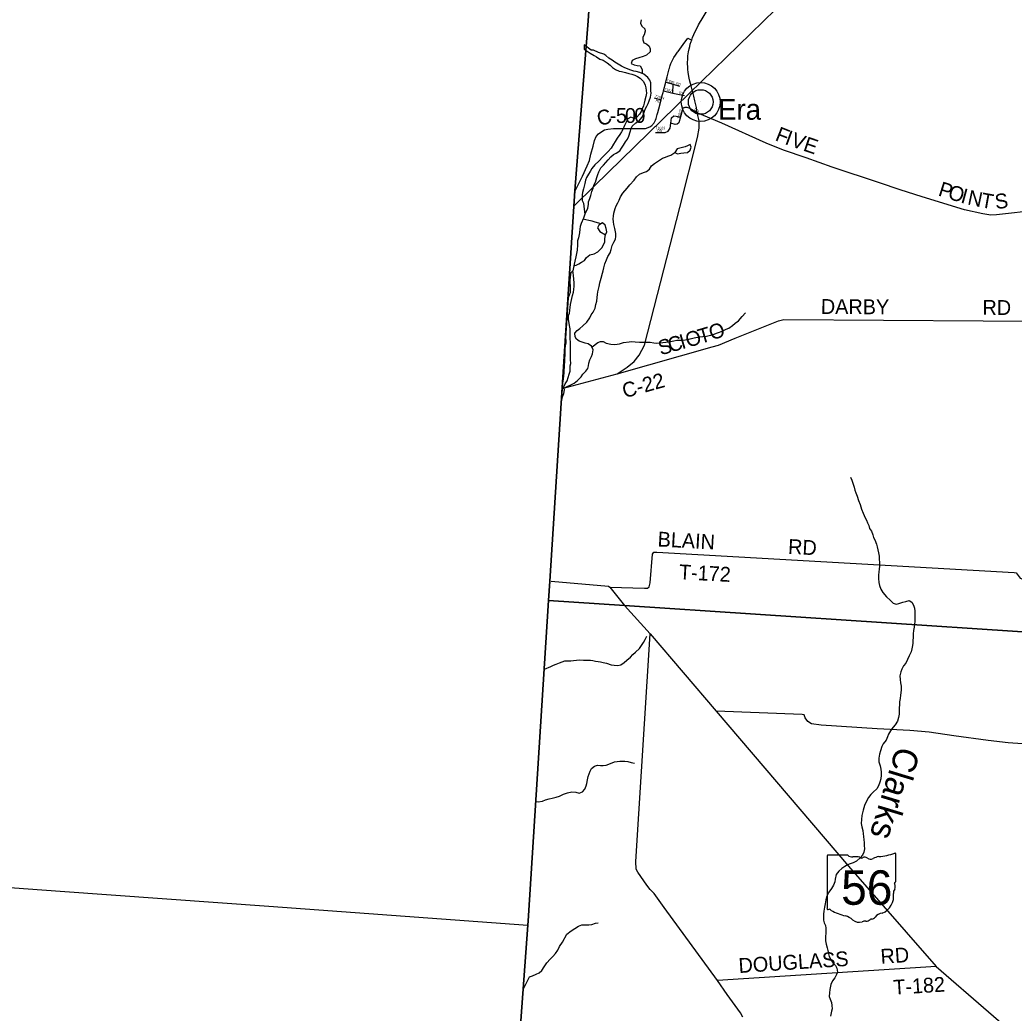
# Model space of a CAD drawing. Extents: x 1643459 to 2064572, y 425441 to 780708.
# Drawn here: x 1746483 to 1766596, y 616581 to 636662 of the extents above; entities that cross this region are included whole.
import ezdxf

# ---------------------------------------------------------------- set-up
doc = ezdxf.new("R2010")
doc.units = 0
for name, color, linetype in [('GE_P_Alignment_100_Curve_Data', 7, 'Continuous'), ('GM_X_City_Street', 7, 'Continuous'), ('GM_X_County', 7, 'Continuous'), ('GM_X_Interchange_Ramps', 7, 'Continuous'), ('GM_X_Interstate_Route', 7, 'Continuous'), ('GM_X_Major_River', 7, 'Continuous'), ('GM_X_Major_River_Text', 7, 'Continuous'), ('GM_X_Minor_Lake', 7, 'Continuous'), ('GM_X_Minor_River', 7, 'Continuous'), ('GM_X_Rail_Line', 7, 'Continuous'), ('GM_X_Section_Text', 7, 'Continuous'), ('GM_X_Township', 7, 'Continuous'), ('GM_X_Township_Road', 7, 'Continuous'), ('GM_X_Township_ROW', 7, 'Continuous'), ('GM_X_Township_Subdivision_Text', 7, 'Continuous'), ('GM_X_Unincorporated_Text', 7, 'Continuous'), ('GM_X_US_Route', 7, 'Continuous'), ('PM_P_Cells', 7, 'Continuous'), ('RD_X_Text', 7, 'Continuous'), ('RD_X_Wall', 7, 'Continuous'), ('ST_Details', 7, 'Continuous')]:
    doc.layers.add(name, color=color, linetype=linetype)

msp = doc.modelspace()

# ---------------------------------------------------------------- linework, layer by layer
at = {"layer": 'GE_P_Alignment_100_Curve_Data'}
for radius in [393, 249]:
    msp.add_circle((1760256, 635002), radius, dxfattribs=at)
at = {"layer": 'GM_X_City_Street'}
for points in [[(1790269, 631741), (1788081, 631718), (1783242, 631666), (1778092, 631612), (1779143, 629082), (1780359, 626159), (1781545, 623306), (1775923, 623680), (1771965, 623943), (1758715, 624823), (1757178, 624925), (1757203, 625316), (1757453, 629228), (1757708, 633208), (1757977, 636642), (1758154, 639332)], [(1755032, 592905), (1755763, 604727), (1756758, 618359), (1756763, 618445), (1757178, 624925), (1758715, 624823), (1771965, 623943), (1775923, 623680), (1781545, 623306), (1781837, 622626), (1785470, 614182), (1787632, 609158), (1789055, 605851), (1790575, 602316), (1791118, 601055), (1793558, 602184), (1795084, 602890), (1794631, 595981)]]:
    msp.add_lwpolyline(points, dxfattribs=at)
at = {"layer": 'GM_X_County'}
for points in [[(1759552, 635405), (1759696, 635362), (1759828, 635324)], [(1759505, 635228), (1759691, 635180), (1759927, 635131)], [(1759691, 635180), (1759696, 635362)], [(1759314, 635088), (1759457, 635049)], [(1759913, 634884), (1759896, 634878), (1759848, 634705), (1759812, 634578), (1759780, 634554), (1759740, 634546), (1759654, 634577)], [(1760184, 634781), (1760020, 634874), (1759980, 634892), (1759934, 634890), (1759924, 634887), (1759913, 634884)], [(1759343, 634384), (1759469, 634387), (1759535, 634383), (1759597, 634410), (1759637, 634472), (1759654, 634577), (1759667, 634685), (1759715, 634719), (1759848, 634705)]]:
    msp.add_lwpolyline(points, dxfattribs=at)
at = {"layer": 'GM_X_Interstate_Route'}
msp.add_lwpolyline([(1792928, 659077), (1789408, 659196), (1786100, 659304), (1784956, 659328), (1781576, 659434), (1779741, 659492), (1773339, 659850), (1771560, 659962), (1771157, 659994), (1759596, 661027), (1759526, 659870), (1759045, 652740), (1758962, 651389), (1758154, 639332), (1757977, 636642), (1757708, 633208), (1757453, 629228), (1757203, 625316), (1757178, 624925), (1756763, 618445), (1756758, 618359), (1755763, 604727), (1755032, 592905)], dxfattribs=at)
at = {"layer": 'GM_X_Major_River_Text'}
for points in [[(1758421, 625192), (1759118, 625175), (1759180, 625174), (1759214, 625196), (1759235, 625280), (1759284, 625860), (1759310, 625902), (1759370, 625900), (1766599, 625487), (1766639, 625483), (1766717, 625372), (1766771, 625352), (1769252, 625185), (1769288, 625191), (1769317, 625233), (1769369, 625594), (1769393, 625623), (1769429, 625637), (1771468, 626355)], [(1772265, 622062), (1771334, 621784), (1771222, 621751), (1771159, 621721), (1771061, 621727), (1767086, 622006), (1766767, 622024), (1766477, 622043), (1766074, 622089), (1765375, 622185), (1764879, 622258), (1764486, 622292), (1763829, 622329), (1762692, 622399), (1762500, 622430), (1762426, 622474), (1762366, 622549), (1762350, 622609), (1762308, 622615), (1760568, 622684)], [(1765022, 617523), (1760593, 617243)]]:
    msp.add_lwpolyline(points, dxfattribs=at)
at = {"layer": 'GM_X_Minor_Lake'}
for points in [[(1757705, 633176), (1757862, 633499), (1757957, 633711), (1758009, 633820), (1758036, 633946), (1758080, 634111), (1758105, 634223), (1758142, 634301), (1758190, 634358), (1758235, 634395), (1758309, 634436), (1758377, 634454), (1758492, 634468), (1758804, 634463), (1759139, 634463), (1759229, 634497), (1759267, 634529), (1759286, 634548), (1759297, 634560), (1759305, 634571), (1759313, 634582), (1759322, 634595), (1759330, 634609), (1759342, 634637), (1759355, 634671), (1759369, 634719), (1759378, 634750), (1759389, 634791), (1759407, 634861), (1759457, 635049), (1759473, 635108), (1759485, 635152), (1759495, 635193), (1759503, 635221), (1759505, 635228), (1759552, 635405), (1759560, 635435), (1759580, 635514), (1759607, 635619), (1759621, 635670), (1759626, 635689), (1759641, 635739), (1759655, 635778), (1759674, 635824), (1759692, 635862), (1759715, 635901), (1759747, 635950), (1759790, 636012), (1759798, 636022), (1759903, 636165), (1759996, 636292), (1760074, 636255)], [(1770000, 630549), (1769738, 630751), (1767875, 632293), (1767488, 632617), (1767305, 632763), (1767251, 632801), (1767205, 632821), (1767083, 632818), (1766239, 632718), (1766124, 632716), (1765966, 632741), (1765594, 632819), (1764734, 633082), (1764288, 633225), (1763876, 633369), (1762914, 633685), (1762390, 633870), (1761928, 634031), (1761582, 634167), (1760684, 634572), (1760184, 634781)], [(1758569, 629508), (1760488, 630050), (1760613, 630088), (1760956, 630230), (1761763, 630549), (1761833, 630579), (1761938, 630603), (1770000, 630549), (1770002, 630601), (1770002, 630601)], [(1761110, 616500), (1761060, 616588), (1760794, 616957), (1760593, 617243), (1759519, 618715), (1759314, 618997), (1759234, 619082), (1759164, 619166), (1758982, 619428), (1758952, 619494), (1758947, 619647), (1759231, 624246)]]:
    msp.add_lwpolyline(points, dxfattribs=at)
at = {"layer": 'GM_X_Minor_River'}
msp.add_lwpolyline([(1742304, 619412), (1747296, 619048), (1751520, 618741), (1756758, 618359), (1756763, 618445), (1757178, 624925), (1757203, 625316), (1757453, 629228), (1757708, 633208), (1757977, 636642), (1758154, 639332), (1758962, 651389), (1759045, 652740), (1759526, 659870), (1759596, 661027), (1759497, 662188)], dxfattribs=at)
at = {"layer": 'GM_X_Rail_Line'}
msp.add_line((1760256, 635002), (1760256, 635002), dxfattribs=at)
at = {"layer": 'GM_X_Township_Road'}
msp.add_lwpolyline([(1757688, 632894), (1758106, 633308), (1760023, 635174), (1763516, 638579)], dxfattribs=at)
at = {"layer": 'GM_X_Township_Subdivision_Text'}
for points in [[(1759735, 633978), (1759789, 633955), (1759851, 633965), (1759917, 633973), (1759986, 633982), (1760040, 634030), (1760060, 634092), (1760045, 634145), (1759988, 634117), (1759944, 634093)], [(1759944, 634093), (1759783, 634052), (1759735, 633978)]]:
    msp.add_lwpolyline(points, dxfattribs=at)
at = {"layer": 'GM_X_Unincorporated_Text'}
for p, q in [((1757899, 636159), (1757896, 636071)), ((1757572, 631040), (1757520, 630224)), ((1757463, 629334), (1757439, 628958))]:
    msp.add_line(p, q, dxfattribs=at)
for points in [[(1757896, 636071), (1757941, 636041), (1758023, 635992), (1758099, 635944), (1758151, 635913), (1758218, 635869), (1758282, 635847), (1758362, 635796), (1758422, 635749), (1758474, 635701), (1758532, 635658), (1758604, 635628), (1758654, 635618), (1758738, 635601), (1758800, 635581), (1758864, 635562), (1758926, 635546), (1758980, 635516), (1759032, 635485), (1759097, 635417), (1759133, 635342), (1759145, 635290), (1759154, 635234), (1759158, 635181), (1759145, 635111), (1759129, 635039), (1759112, 634975), (1759098, 634925), (1759075, 634867), (1759051, 634813), (1759021, 634756), (1758958, 634687), (1758908, 634669), (1758842, 634695), (1758785, 634663), (1758745, 634597), (1758712, 634527), (1758680, 634449), (1758651, 634397), (1758617, 634343), (1758566, 634273), (1758525, 634203), (1758491, 634147), (1758448, 634069), (1758386, 633999), (1758331, 633949), (1758273, 633891), (1758194, 633803), (1758117, 633732), (1758056, 633658), (1758022, 633600), (1757989, 633546), (1757949, 633478), (1757926, 633421), (1757912, 633351), (1757901, 633299), (1757885, 633243), (1757862, 633175), (1757856, 633125), (1757860, 633074), (1757857, 633012), (1757885, 632956), (1757893, 632896), (1757911, 632725)], [(1757911, 632725), (1757940, 632779), (1757970, 632853), (1757987, 632931), (1757989, 632983), (1758012, 633054), (1758036, 633114), (1758057, 633192), (1758078, 633258), (1758094, 633320), (1758125, 633382), (1758155, 633478), (1758174, 633539), (1758194, 633589), (1758239, 633669), (1758293, 633723), (1758384, 633830), (1758435, 633892), (1758491, 633940), (1758548, 633966), (1758622, 634012), (1758655, 634068), (1758691, 634130), (1758732, 634196), (1758778, 634250), (1758805, 634312), (1758830, 634396), (1758846, 634464), (1758870, 634516), (1758941, 634578), (1759010, 634618), (1759066, 634686), (1759099, 634756), (1759121, 634816), (1759142, 634868), (1759168, 634920), (1759195, 634974), (1759215, 635024), (1759238, 635103), (1759252, 635179), (1759248, 635231), (1759246, 635392), (1759228, 635444), (1759184, 635496), (1759106, 635563), (1759024, 635596), (1758952, 635618), (1758900, 635626), (1758824, 635649), (1758708, 635698), (1758652, 635724), (1758587, 635767), (1758521, 635807), (1758463, 635848), (1758399, 635888), (1758335, 635942), (1758295, 635971), (1758190, 636006), (1758085, 636047), (1758043, 636051), (1757899, 636159)], [(1757911, 632725), (1757903, 632711), (1757883, 632653), (1757838, 632545), (1757815, 632483), (1757811, 632428), (1757805, 632356), (1757784, 632256), (1757767, 632198), (1757763, 632111), (1757754, 632005), (1757741, 631941), (1757727, 631871), (1757708, 631784), (1757694, 631726), (1757669, 631590)], [(1757669, 631590), (1757631, 631549), (1757619, 631521), (1757614, 631451), (1757611, 631406)], [(1757665, 631088), (1757680, 631154), (1757688, 631208), (1757695, 631275), (1757693, 631339), (1757688, 631427), (1757682, 631488), (1757677, 631552), (1757669, 631590)], [(1757611, 631406), (1757616, 631234), (1757614, 631152), (1757572, 631040)], [(1757613, 630273), (1757616, 630334), (1757618, 630418), (1757603, 630481), (1757593, 630533), (1757584, 630601), (1757584, 630682), (1757605, 630733), (1757607, 630795), (1757615, 630846), (1757624, 630906), (1757665, 631088)], [(1757520, 630224), (1757526, 630188), (1757527, 630126), (1757517, 630074), (1757510, 630010), (1757507, 629934), (1757507, 629884), (1757504, 629813), (1757499, 629741), (1757495, 629689), (1757492, 629633), (1757490, 629583), (1757485, 629531), (1757480, 629459), (1757476, 629409), (1757467, 629345), (1757463, 629334)], [(1757554, 629366), (1757593, 629497), (1757612, 629559), (1757617, 629612), (1757617, 629669), (1757627, 629717), (1757624, 629796), (1757625, 630002), (1757622, 630081), (1757621, 630149), (1757615, 630215), (1757613, 630273)], [(1757439, 628958), (1757444, 628973), (1757458, 629041), (1757485, 629111), (1757500, 629179), (1757484, 629243), (1757517, 629305), (1757554, 629366)]]:
    msp.add_lwpolyline(points, dxfattribs=at)
at = {"layer": 'GM_X_US_Route'}
for points in [[(1759050, 636663), (1759038, 636593), (1759065, 636535), (1759127, 636482), (1759135, 636432), (1759112, 636362), (1759088, 636310), (1759083, 636256), (1759105, 636201), (1759157, 636179), (1759213, 636131), (1759232, 636074), (1759234, 636014), (1759161, 635950), (1759093, 635922), (1759003, 635893), (1758936, 635877), (1758870, 635841), (1758851, 635781), (1758909, 635751), (1758969, 635740), (1759031, 635736), (1759075, 635662), (1759069, 635586)], [(1757958, 636133), (1757958, 636133)], [(1757490, 629219), (1757695, 629317), (1757761, 629373), (1757838, 629445), (1757873, 629499), (1757929, 629561), (1757976, 629615), (1757988, 629665), (1757992, 629723), (1758011, 629791), (1758050, 629853), (1758064, 629908), (1758079, 629994), (1758049, 630062), (1757981, 630111), (1757921, 630129), (1757855, 630146), (1757795, 630168), (1757743, 630204), (1757714, 630257), (1757712, 630329), (1757754, 630381), (1757809, 630421), (1757873, 630475), (1757952, 630553), (1758013, 630639), (1758043, 630699), (1758082, 630751), (1758119, 630831), (1758135, 630907), (1758154, 630973), (1758160, 631051), (1758169, 631112), (1758175, 631166), (1758200, 631272), (1758218, 631344), (1758245, 631438), (1758268, 631539), (1758284, 631591), (1758299, 631651), (1758319, 631727), (1758348, 631811), (1758379, 631877), (1758423, 631949), (1758446, 632023), (1758466, 632100), (1758501, 632168), (1758531, 632226), (1758538, 632280), (1758536, 632344), (1758517, 632441), (1758499, 632523), (1758490, 632577), (1758486, 632637), (1758493, 632694), (1758499, 632754), (1758524, 632846), (1758544, 632902), (1758577, 632962), (1758605, 633018), (1758636, 633082), (1758684, 633160), (1758767, 633258), (1758820, 633328), (1758909, 633422), (1758955, 633492), (1759016, 633544), (1759100, 633574), (1759159, 633597), (1759217, 633645), (1759262, 633711), (1759322, 633757), (1759399, 633811), (1759483, 633865), (1759542, 633884), (1759592, 633904), (1759654, 633926), (1759735, 633978)], [(1757685, 631692), (1757734, 631704), (1757788, 631728), (1757844, 631762), (1757903, 631797), (1757949, 631859), (1758010, 631915), (1758100, 631935), (1758175, 631971), (1758254, 632053), (1758298, 632125), (1758317, 632175), (1758319, 632243), (1758330, 632317), (1758358, 632379), (1758343, 632446), (1758323, 632510), (1758271, 632560), (1758195, 632515), (1758170, 632459), (1758214, 632386), (1758330, 632317)], [(1758243, 632540), (1758121, 632575), (1758061, 632590), (1757991, 632604), (1757870, 632630)], [(1757675, 631639), (1757676, 631643)], [(1757598, 631320), (1757599, 631317)], [(1758059, 630050), (1758176, 630138), (1758228, 630158), (1758284, 630159), (1758346, 630125), (1758438, 630106), (1758522, 630102), (1758613, 630115), (1758695, 630137), (1758808, 630154), (1758858, 630160), (1758928, 630152), (1759016, 630149), (1759070, 630149), (1759152, 630149), (1759231, 630144), (1759309, 630134), (1759361, 630129), (1759427, 630131), (1759487, 630137), (1759549, 630148), (1759614, 630156), (1759710, 630172), (1759774, 630185), (1759836, 630189), (1759896, 630187), (1759995, 630198), (1760045, 630216), (1760123, 630236), (1760230, 630251), (1760302, 630261), (1760372, 630266), (1760426, 630278), (1760495, 630292), (1760575, 630328), (1760633, 630347), (1760704, 630373), (1760774, 630407), (1760827, 630431), (1760899, 630486), (1760956, 630528), (1761018, 630580), (1761097, 630662), (1761164, 630740)], [(1763285, 627418), (1763315, 627354), (1763343, 627275), (1763360, 627217), (1763376, 627155), (1763397, 627100), (1763419, 627030), (1763449, 626947), (1763480, 626867), (1763511, 626772), (1763545, 626686), (1763580, 626597), (1763612, 626547), (1763628, 626495), (1763657, 626442), (1763673, 626382), (1763709, 626324), (1763736, 626253), (1763754, 626199), (1763780, 626147), (1763815, 626062), (1763827, 626008), (1763840, 625950), (1763854, 625889), (1763864, 625817), (1763869, 625751), (1763871, 625696), (1763870, 625620), (1763868, 625556), (1763859, 625504), (1763855, 625432), (1763852, 625371), (1763860, 625289), (1763871, 625229), (1763903, 625150), (1763943, 625084), (1764012, 624995), (1764090, 624928), (1764152, 624870), (1764212, 624851), (1764262, 624865), (1764342, 624889), (1764407, 624903), (1764471, 624922), (1764529, 624888), (1764562, 624827), (1764578, 624771), (1764588, 624705), (1764589, 624639), (1764591, 624588), (1764590, 624496), (1764584, 624444), (1764573, 624384), (1764563, 624313), (1764556, 624247), (1764554, 624177), (1764549, 624115), (1764547, 624063), (1764541, 624012), (1764526, 623948), (1764512, 623884), (1764475, 623802), (1764440, 623730), (1764404, 623658), (1764359, 623602), (1764325, 623534), (1764302, 623482), (1764286, 623402), (1764291, 623325), (1764301, 623261), (1764310, 623191), (1764310, 623112), (1764299, 623010), (1764288, 622942), (1764280, 622871), (1764277, 622817), (1764273, 622743), (1764270, 622675), (1764268, 622623), (1764260, 622556), (1764239, 622484), (1764192, 622410), (1764118, 622320), (1764057, 622218), (1764032, 622168), (1764008, 622100), (1763947, 622028), (1763917, 621972), (1763894, 621884), (1763871, 621814), (1763861, 621733), (1763862, 621659), (1763884, 621581), (1763901, 621510), (1763907, 621450), (1763906, 621394), (1763900, 621320), (1763881, 621251), (1763851, 621175), (1763820, 621113), (1763748, 621049)], [(1757505, 623702), (1757629, 623703), (1757681, 623712), (1757745, 623718), (1757804, 623720), (1757882, 623717), (1757954, 623719), (1758024, 623717), (1758076, 623708), (1758126, 623698), (1758182, 623690), (1758232, 623681), (1758284, 623667), (1758348, 623655), (1758443, 623624), (1758505, 623616), (1758581, 623609), (1758643, 623623), (1758710, 623671), (1758764, 623719), (1758833, 623780), (1758885, 623834), (1758938, 623878), (1759018, 623952), (1759061, 624010), (1759097, 624076), (1759130, 624132), (1759168, 624204)], [(1757093, 623537), (1757225, 623587), (1757276, 623616), (1757330, 623637), (1757401, 623661), (1757505, 623702)], [(1757480, 621007), (1757562, 621035), (1757648, 621056), (1757729, 621048), (1757795, 621027), (1757863, 621055), (1757913, 621109), (1757940, 621173), (1757950, 621223), (1757965, 621300), (1757979, 621362), (1757998, 621418), (1758020, 621474), (1758045, 621524), (1758105, 621574), (1758167, 621592), (1758230, 621589), (1758286, 621587), (1758342, 621591), (1758398, 621612), (1758511, 621660), (1758619, 621676), (1758723, 621675), (1758782, 621665), (1758850, 621648), (1758914, 621632)], [(1756907, 620868), (1756971, 620851), (1757053, 620868), (1757118, 620894), (1757188, 620915), (1757252, 620928), (1757333, 620947), (1757399, 620966), (1757480, 621007)], [(1763748, 621049), (1763697, 621001), (1763651, 620943), (1763598, 620837), (1763569, 620781), (1763541, 620687), (1763532, 620629), (1763518, 620575), (1763511, 620494), (1763499, 620412), (1763518, 620350), (1763536, 620273), (1763543, 620203), (1763549, 620153), (1763554, 620084), (1763560, 620028), (1763566, 619968), (1763569, 619904), (1763559, 619833), (1763528, 619777), (1763482, 619723), (1763411, 619652), (1763340, 619616), (1763282, 619600), (1763228, 619576), (1763172, 619548), (1763111, 619505), (1763053, 619451), (1762998, 619383), (1762975, 619292), (1762969, 619234), (1762944, 619164), (1762904, 619098), (1762845, 619026), (1762806, 618948), (1762788, 618874), (1762775, 618787), (1762763, 618721), (1762750, 618645), (1762740, 618579), (1762737, 618517), (1762741, 618458), (1762754, 618408), (1762778, 618350), (1762786, 618297), (1762789, 618245), (1762785, 618193), (1762781, 618139), (1762778, 618042), (1762796, 617976), (1762815, 617900), (1762827, 617849), (1762838, 617779), (1762858, 617727), (1762895, 617650), (1762939, 617592), (1762983, 617541), (1763007, 617489), (1763024, 617410), (1763002, 617358), (1762971, 617294), (1762925, 617230), (1762888, 617162), (1762865, 617060), (1762859, 616993), (1762852, 616915), (1762876, 616861), (1762903, 616798), (1762911, 616734), (1762913, 616670), (1762904, 616620), (1762885, 616521)], [(1757458, 618012), (1757550, 618175), (1757636, 618247), (1757713, 618293), (1757782, 618341), (1757854, 618368), (1757932, 618366), (1757994, 618366), (1758054, 618375), (1758129, 618397), (1758183, 618409)], [(1756664, 617060), (1756792, 617312), (1756851, 617334), (1756930, 617371), (1756986, 617392), (1757045, 617444), (1757090, 617515), (1757143, 617595), (1757208, 617672), (1757265, 617726), (1757316, 617785), (1757367, 617855), (1757402, 617925), (1757458, 618012)]]:
    msp.add_lwpolyline(points, dxfattribs=at)
at = {"layer": 'RD_X_Text'}
msp.add_lwpolyline([(1757232, 625314), (1758391, 625211), (1758421, 625192), (1758715, 624823), (1759231, 624246), (1760568, 622684), (1763244, 619552), (1765022, 617523), (1767140, 615688), (1768855, 614819), (1771492, 613520), (1772414, 613091), (1772539, 613016), (1772653, 612916), (1773673, 611884), (1773774, 611775), (1773945, 611670), (1774091, 611580), (1776024, 610826)], dxfattribs=at)
at = {"layer": 'RD_X_Wall'}
msp.add_lwpolyline([(1757453, 629211), (1758569, 629508), (1758768, 629638), (1758910, 629755), (1759010, 629881), (1759119, 630086), (1759832, 632867), (1760193, 634283), (1760223, 634476), (1760227, 634624), (1760184, 634781), (1760179, 634827), (1760169, 634888), (1760158, 634943), (1760138, 635025), (1760115, 635118), (1760094, 635204), (1760090, 635220), (1760061, 635331), (1760038, 635423), (1760024, 635487), (1760011, 635558), (1760004, 635604), (1759998, 635656), (1759994, 635715), (1759992, 635774), (1759996, 635894), (1759996, 635900), (1759999, 635936), (1760011, 636017), (1760022, 636075), (1760033, 636127), (1760046, 636174), (1760064, 636228), (1760074, 636255), (1760093, 636305), (1760118, 636365), (1760212, 636565), (1760418, 636909)], dxfattribs=at)
at = {"layer": 'ST_Details'}
for p, q in [((1762811, 619753), (1762811, 618697)), ((1763232, 619771), (1762824, 619771)), ((1764203, 619245), (1764203, 619798)), ((1764203, 619245), (1764203, 619245))]:
    msp.add_line(p, q, dxfattribs=at)
for centre, radius, start, end in [((1762827, 619755), 16.1, 98.1301, 188.1301), ((1763329, 619894), 156, 231.6195, 271.1119), ((1763381, 619178), 562, 80.4867, 94.9883), ((1763508, 619761), 45.1, 219.7921, 297.1024), ((1763575, 619639), 93.8, 54.4667, 119.1411), ((1763696, 619806), 113, 233.8562, 294.8282), ((1763895, 619449), 297, 97.3462, 120.7689), ((1763707, 621212), 1476, 275.8445, 288.9065), ((1764187, 619800), 15.5, 351.8621, 97.738), ((1764258, 619013), 105, 136.8065, 186.9296), ((1764199, 619204), 24, 107.944, 210.337), ((1764047, 619134), 144, 340.033, 23.6496), ((1764186, 619243), 16.6, 289.6038, 7.7341), ((1763790, 618943), 369, 292.3089, 8.9858), ((1762827, 618694), 16.3, 171.9584, 258.3066), ((1762829, 618802), 124, 267.339, 280.6039), ((1762855, 618636), 44.8, 29.7484, 93.2717), ((1763420, 619585), 1066, 240.4129, 257.1985), ((1763102, 618222), 334, 47.1842, 75.836), ((1763703, 618449), 31.8, 65.7517, 132.6484), ((1763689, 618594), 119, 282.8732, 323.2771), ((1763945, 618400), 202, 94.4031, 142.5768), ((1763463, 618630), 212, 230.7004, 286.2918), ((1763585, 618265), 174, 85.6951, 111.2099), ((1763601, 618551), 113, 268.777, 315.5493)]:
    msp.add_arc(centre, radius, start, end, dxfattribs=at)

# ---------------------------------------------------------------- texts
at = {"layer": 'GM_X_Interchange_Ramps'}
msp.add_text('Clarks', height=500.1, rotation=253.1181, dxfattribs=at).set_placement((1764222, 621998))
at = {"layer": 'GM_X_Major_River'}
for s, rotation, p in [('BLAIN', 356.8698, (1759378, 626017)), ('RD', 357.0388, (1762018, 625867)), ('T-172', 356.9131, (1759810, 625354)), ('RD', 3.9449, (1763904, 617575)), ('DOUGLASS', 3.7453, (1761031, 617390)), ('T-182', 3.6632, (1764161, 616950))]:
    msp.add_text(s, height=300, rotation=rotation, dxfattribs=at).set_placement(p)
at = {"layer": 'GM_X_Section_Text'}
for s, rotation, p in [('C', 15.8095, (1758204, 634511)), ('5', 359.5622, (1758540, 634580)), ('0', 359.6063, (1758723, 634579)), ('0', 1.2544, (1758916, 634578)), ('-', 2.7959, (1758422, 634575)), ('F', 338.4315, (1761744, 634233)), ('I', 339.9202, (1761940, 634156)), ('V', 340.8299, (1762060, 634112)), ('E', 341.0307, (1762311, 634025)), ('P', 342.4756, (1765044, 633114)), ('O', 342.728, (1765238, 633053)), ('I', 344.5872, (1765500, 632972)), ('N', 347.985, (1765638, 632934)), ('T', 349.8723, (1765907, 632877)), ('S', 6.9788, (1766225, 632835)), ('DARBY', 359.6208, (1762686, 630718)), ('RD', 359.5064, (1765955, 630700)), ('O', 16.0059, (1759995, 630035)), ('T', 16.3321, (1760250, 630108)), ('O', 19.6412, (1760483, 630177)), ('S', 16.0061, (1759445, 629877)), ('C', 16.0028, (1759639, 629933)), ('I', 16.0078, (1759876, 630001)), ('C-22', 15.6153, (1758716, 629011))]:
    msp.add_text(s, height=300, rotation=rotation, dxfattribs=at).set_placement(p)
at = {"layer": 'GM_X_Township'}
for s, rotation, p in [('T', 341.1374, (1759559, 635417)), ('1', 341.1108, (1759593, 635406)), ('0', 341.1263, (1759622, 635396)), ('2', 341.1351, (1759651, 635386)), ('6', 342.7851, (1759682, 635376)), ('RD', 344.4724, (1759752, 635356)), ('T1025', 344.0513, (1759515, 635242)), ('RD', 348.1171, (1759818, 635167)), ('T1024', 344.0571, (1759326, 635101)), ('RD', 341.5632, (1759339, 635011)), ('T1022', 74.0546, (1759825, 634659)), ('RD', 332.0959, (1760115, 634832)), ('T1023', 0, (1759341, 634450)), ('RD', 0, (1759380, 634391))]:
    msp.add_text(s, height=50, rotation=rotation, dxfattribs=at).set_placement(p)
at = {"layer": 'GM_X_Township_ROW'}
msp.add_text('Era', height=417, rotation=0, dxfattribs=at).set_placement((1760608, 634643))
at = {"layer": 'PM_P_Cells'}
msp.add_text('56', height=1, rotation=0, dxfattribs=at).set_placement((1763239, 619082))
for s in ['s', 'r']:
    msp.add_text(s, height=1, dxfattribs=at).set_placement((1763491, 619155))
at = {"layer": 'ST_Details'}
msp.add_text('56', height=696.1, dxfattribs=at).set_placement((1763098, 618771))

doc.saveas('drawing.dxf')
